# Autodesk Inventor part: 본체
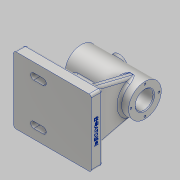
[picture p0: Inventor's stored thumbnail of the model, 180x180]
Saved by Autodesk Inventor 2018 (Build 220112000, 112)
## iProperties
Created: 2022-06
Part Number: 본체
Material: 알루미늄 6061
Document SubType Name: Modeling
Designer: home
Density: 2.7 g/cm^3
Appearance: 알루미늄 - 평지
Mass: 632.935 g
Surface Area: 512.719 cm^2
Volume: 234.42 cm^3
Author: home
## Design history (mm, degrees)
sketch "스케치1"
  geometry: L1 (50, -43)-(-50, -43); L2 (-50, -43)-(-50, 43); L3 (-50, 43)-(50, 43); L4 (50, 43)-(50, -43); 3 further points
  constraints: 8 end point, 2 midpoint, 2 parallel, 1 horizontal, 1 horizontal alignment, 1 perpendicular, 1 vertical alignment
  dimensions: "d0" = 100 distance of L1.start L1.end; "d1" = 86 distance of L3.end L1.start
extrude "돌출1" new body sketch "스케치1" distance "d2" = 15; taper "d3" = 0 deg
sketch "스케치2"
  geometry: L1 (-71.574, 72)-(71.574, 72); L2 (-50, 0)-(50, 0) reference; L3 (-35, 86.5)-(27, 86.5); L4 (27, 86.5)-(27, 83.5); L5 (27, 83.5)-(47, 83.5); L6 (47, 83.5)-(47, 93); L7 (47, 93)-(-35, 93); L8 (-35, 93)-(-35, 86.5); L9 (-50, 0)-(-50, 15) reference; 2 further points
  constraints: 14 end point, 5 perpendicular, 2 horizontal, 1 midpoint, 1 vertical alignment
  dimensions: "d4" = 72 distance between parallel lines of L2 L1; "d5" = 15 distance between parallel lines of L9 L8; "d6" = 82 distance of L6.end L7.end; "d7" = 23 diameter of L5 L1; "d9" = 42 diameter of L7 L1; "d10" = 29 diameter of L3 L1; "d11" = 20 distance between parallel lines of L6 L4; "d12" = 121.57388 distance from line of L1.end L9
revolve "회전1" sketch "스케치2" stored, may be unused: angle "d13" = 90 deg
sketch "스케치3"
  geometry: L1 (-24, 27)-(-12, 27); L2 (-24, 20)-(-12, 20); L3 (-12, 34)-(-24, 34); L4 (-50, 43)-(50, 43) reference; L5 (-50, -43)-(-50, 43) reference; A1 r 7 centre (-24, 27) between (-24, 34) and (-24, 20); A2 r 7 centre (-12, 27) between (-12, 20) and (-12, 34); 2 further points
  constraints: 8 end point, 4 point on circle, 4 tangent, 2 centre point, 1 horizontal, 1 midpoint, 1 parallel
  dimensions: "d14" = 12 distance of L1.start L1.end; "d15" = 7 radius of A2; "d80" = 26 distance from line of L5 L1.start; "d81" = 16 distance between parallel lines of L4 L1
extrude "돌출2" join sketch "스케치3" distance "d18" = 3; taper "d19" = 0 deg
sketch "스케치4"
  geometry: L1 (-24, 34)-(-12, 34) reference; L2 (-12, 20)-(-24, 20) reference; L3 (50, 43)-(-50, 43) reference; L4 (-50, 43)-(-50, -43) reference; L5 (-50, -43)-(50, -43) reference; L6 (50, -43)-(50, 43) reference; L7 (-24, 27)-(-12, 27); L8 (-24, 23)-(-12, 23); L9 (-12, 31)-(-24, 31); A1 r 7 centre (-24, 27) between (-24, 34) and (-24, 20) reference; A2 r 7 centre (-12, 27) between (-12, 20) and (-12, 34) reference; A3 r 4 centre (-24, 27) between (-24, 31) and (-24, 23); A4 r 4 centre (-12, 27) between (-12, 23) and (-12, 31); 2 further points
  constraints: 8 end point, 4 point on circle, 4 tangent, 2 centre point, 1 horizontal, 1 midpoint, 1 parallel
  dimensions: "d20" = 4 radius of A4
extrude "돌출3" cut sketch "스케치4" extent not by distance; stored distance "d21" = 3; taper "d22" = 0 deg
fillet "모깎기1" dims "d26" = 3
fillet "모깎기2" dims "d27" = 3
sketch "스케치5"
  geometry: C1 r 11.5 at (0, 0) reference; 2 further points
  constraints: 1 vertical alignment
  dimensions: "d28" = 18 distance of C1.centre point (0, 18)
hole "구멍1" sketch "스케치5" at (0, 18) diameter "d29" = 2.459; stored, may be unused: countersink angle "d33" = 90 deg, drill point angle "d35" = 118 deg; dims "d30" = 8, "d31" = 4, "d32" = 2, "d34" = 10
node "작업 평면1"
node "작업 평면2"
sketch "스케치6"
  geometry: L1 (19, 72)-(5, 15); L2 (61, 72)-(75, 15); L3 (23, 15)-(3, 15) reference; L4 (77, 15)-(57, 15) reference; L5 (-3, 0)-(-3, 12) reference; L6 (83, 12)-(83, 0) reference; L7 (5, 15)-(75, 15); A1 r 21 centre (40, 72) between (19, 72) and (61, 72) reference; 1 further point
  constraints: 6 end point, 2 horizontal alignment, 2 point on circle, 2 point on line, 1 collinear
  dimensions: "d40" = 8 distance from line of L1.end L5; "d41" = 8 distance from line of L6 L2.end
extrude "돌출4" join sketch "스케치6" distance "d42" = 10; taper "d43" = 0 deg
sketch "스케치7"
  geometry: L1 (-21.897, 51)-(-35, 15); L2 (-47, 15)-(47, 15) reference; L3 (-35, 51)-(47, 51) reference; L4 (-24, 15)-(-34, 15) reference; L5 (-24, 15)-(-12, 15) reference; L6 (-50, 0)-(-50, 12) reference; 1 further point
  constraints: 2 end point, 2 point on line
  dimensions: "d44" = 70 deg angle of L2 L1; "d45" = 15 distance from line of L6 L1.end
feature "리브1" sketch "스케치7" dims "d46" = 1, "d47" = 10, "d48" = 0, "d49" = 0, "d50" = 1, "d51" = 1
fillet "모깎기3" dims "d52" = 3
fillet "모깎기4" dims "d53" = 3
node "작업 평면3"
sketch "스케치8"
  geometry: L1 (35, 21)-(35, -21) reference; C1 r 11 at (10, 0); 1 further point
  constraints: 1 centre point, 1 horizontal alignment
  dimensions: "d55" = 11 radius of C1; "d56" = 25 distance from line of L1 C1.centre
extrude "돌출5" join sketch "스케치8" stored distance "d57" = 10; taper "d58" = 0 deg
sketch "스케치9"
  geometry: C1 r 11 at (0, 0) reference; C2 r 7 at (0, 0); 1 further point
  constraints: 1 centre point, 1 coincident
  dimensions: "d59" = 7 radius of C2
extrude "돌출7" cut sketch "스케치9" distance "d62" = 4; taper "d63" = 0 deg
sketch "스케치10"
  geometry: C1 r 7 at (0, 0) reference; 2 further points
  constraints: 1 coincident
hole "구멍2" sketch "스케치10" at (0, 0) diameter "d64" = 6; stored, may be unused: countersink angle "d68" = 90 deg, drill point angle "d70" = 0 deg; dims "d65" = 8, "d66" = 4, "d67" = 2, "d69" = 10
feature "스레드1" dims "d71" = 10, "d72" = 0
fillet "모깎기5" dims "d73" = 3
chamfer "모따기1" distance "d74" = 1; stored, may be unused: second distance "d75" = 2, angle "d76" = 45 deg
sketch "스케치11"
  geometry: L1 (80, 0)-(0, 0) reference; 3 further points
  constraints: 1 midpoint, 1 vertical alignment, 1 other
  dimensions: "d77" = 6 distance from line of L1 point (40, 6)
feature "엠보싱1" sketch "스케치11" dims "d0" = 100, "d1" = 86, "d78" = 0.5, "d79" = 0
node "솔리드1"
pattern_linear "직사각형 패턴1" dims "d25" = 54
pattern_circular "원형 패턴1" dims angle "d37" = 360 deg
mirror "미러1"
node "투영된 루프1"
node "투영된 루프2"
node "투영된 루프3"
other parameters: "d39" = -15, "d54" = 96
